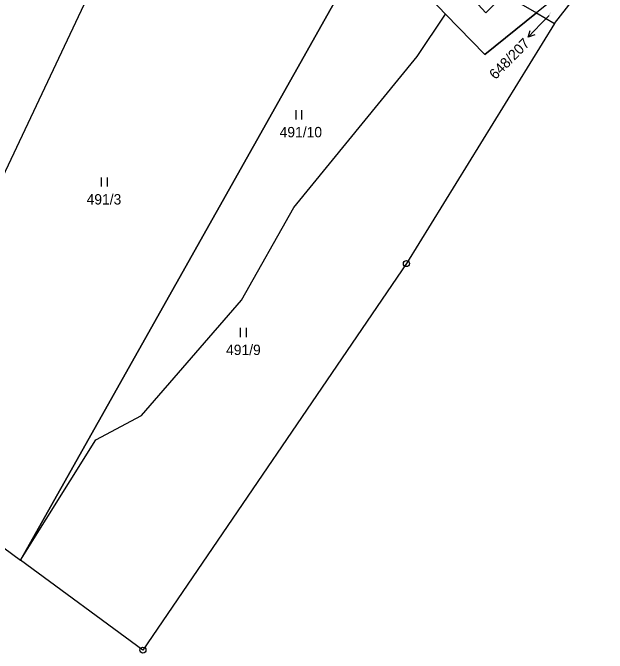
# Model space of a CAD drawing. Extents: x -654083 to -650132, y -1099819 to -1096699.
# Drawn here: x -650329 to -650231.4, y -1099123.7 to -1099018.6 of the extents above; entities that cross this region are included whole.
import ezdxf

# ---------------------------------------------------------------- set-up
doc = ezdxf.new("R2010")
doc.units = 0
for name, color, linetype in [('Geodetické body', 7, 'Continuous'), ('Obvody jako plochy', 7, 'Continuous'), ('Parcelní čísla', 7, 'Continuous'), ('Prvky pro prodl_ par_ č_', 7, 'Continuous'), ('Značky kultur', 7, 'Continuous')]:
    doc.layers.add(name, color=color, linetype=linetype)

msp = doc.modelspace()

# ---------------------------------------------------------------- linework, layer by layer
at = {"layer": 'Geodetické body'}
for centre, radius in [((-650264.38, -1099059.77), 0.5), ((-650264.38, -1099059.77), 0.5), ((-650264.38, -1099059.77), 0.5), ((-650264.38, -1099059.77), 0.001), ((-650264.38, -1099059.77), 0.001), ((-650264.38, -1099059.77), 0.001), ((-650307.62, -1099123.21), 0.5), ((-650307.62, -1099123.21), 0.001)]:
    msp.add_circle(centre, radius, dxfattribs=at)
at = {"layer": 'Obvody jako plochy'}
for points in [[(-650312.23, -1099006.49), (-650351.95, -1099090.56), (-650356.09, -1099087.51), (-650362.41, -1099078.79), (-650379.8, -1099066.99), (-650333.65, -1098975.09), (-650316.9, -1098973.53)], [(-650305.43, -1098996.97), (-650297.22, -1099000.04), (-650289.44, -1098990.97), (-650261.34, -1099007.71), (-650251.34, -1099018.62), (-650248.3, -1099015.54), (-650243.03, -1099018.62), (-650251.52, -1099025.46), (-650257.99, -1099018.84), (-650270.13, -1099006.07), (-650285.42, -1098994.55), (-650299.64, -1099011.71), (-650312.23, -1099006.49), (-650316.9, -1098973.53), (-650308.57, -1098978.96), (-650305.97, -1098987.31)], [(-650299.64, -1099011.71), (-650312.23, -1099006.49), (-650351.95, -1099090.56), (-650327.69, -1099108.43), (-650270.13, -1099006.07), (-650285.42, -1098994.55)], [(-650270.13, -1099006.07), (-650327.69, -1099108.43), (-650315.33, -1099088.71), (-650307.84, -1099084.7), (-650291.45, -1099065.78), (-650282.84, -1099050.59), (-650262.61, -1099025.81), (-650257.99, -1099018.84)], [(-650240.07, -1099020.38), (-650231.44, -1099009.27), (-650243.03, -1099018.62)], [(-650262.61, -1099025.81), (-650257.99, -1099018.84), (-650251.52, -1099025.46), (-650243.03, -1099018.62), (-650240.07, -1099020.38), (-650264.38, -1099059.77), (-650307.62, -1099123.21), (-650327.69, -1099108.43), (-650315.33, -1099088.71), (-650307.84, -1099084.7), (-650291.45, -1099065.78), (-650282.84, -1099050.59)]]:
    msp.add_lwpolyline(points, close=True, dxfattribs=at)
at = {"layer": 'Prvky pro prodl_ par_ č_'}
for p, q in [((-650240.96, -1099019.06), (-650242.3, -1099020.45)), ((-650242.3, -1099020.45), (-650244.39, -1099022.6))]:
    msp.add_line(p, q, dxfattribs=at)
msp.add_lwpolyline([(-650243.33, -1099022.23), (-650244.39, -1099022.6), (-650244.05, -1099021.54)], dxfattribs=at)
at = {"layer": 'Značky kultur'}
for p, q in [((-650282.55, -1099034.61), (-650282.55, -1099036.11)), ((-650281.53, -1099036.11), (-650281.53, -1099034.61)), ((-650314.47, -1099045.65), (-650314.47, -1099047.15)), ((-650313.45, -1099047.15), (-650313.45, -1099045.65)), ((-650291.66, -1099070.34), (-650291.66, -1099071.84)), ((-650290.64, -1099071.84), (-650290.64, -1099070.34))]:
    msp.add_line(p, q, dxfattribs=at)

# ---------------------------------------------------------------- texts
at = {"layer": 'Parcelní čísla'}
msp.add_text('648/207', height=0.1, rotation=51.885, dxfattribs=at).set_placement((-650240.96, -1099019.06))
for s, p in [('491/10', (-650285.18, -1099039.05)), ('491/3', (-650316.85, -1099050.08)), ('491/9', (-650293.97, -1099074.78))]:
    msp.add_text(s, height=1.7, dxfattribs=at).set_placement(p)
at = {"layer": 'Prvky pro prodl_ par_ č_'}
msp.add_text('648/207', height=1.7, rotation=45.423, dxfattribs=at).set_placement((-650249.77, -1099029.67))

doc.saveas('drawing.dxf')
